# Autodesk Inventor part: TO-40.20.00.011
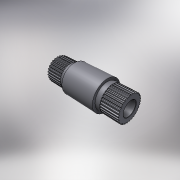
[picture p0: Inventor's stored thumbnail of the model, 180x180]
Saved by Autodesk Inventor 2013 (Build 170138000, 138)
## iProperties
Created: 2012-02
Part Number: TO-40.20.00.011
Material: Steel, Mild
Document SubType Name: Modeling
Designer: tedescj
Mass: 8156.12 g
Surface Area: 1203.33 cm^2
Volume: 1037.67 cm^3
Density: 7.86 g/cm^3
Author: tedescj
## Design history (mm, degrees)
sketch "Sketch1"
  geometry: C1 r 40 at (-44.134, 0) reference; 2 further points
  constraints: 1 centre point, 3 other
extrude "Extrusion1" new body sketch "Sketch1" stored distance "d0" = 242; taper "d1" = 0 deg
sketch "Sketch2"
  geometry: C1 r 48.268 at (-44.134, 0) reference; 1 further point
  constraints: 1 centre point, 2 other
extrude "Extrusion2" join sketch "Sketch2" stored distance "d2" = 106; taper "d3" = 0 deg
feature "Base1"
feature "Base2"
combine "Combine1"
  body "Solid2"
combine "Combine2"
  body "Solid3"
hole "Hole1" diameter "d6" = 45; stored, may be unused: countersink angle "d10" = 90 deg, drill point angle "d12" = 118 deg; dims "d4" = 10, "d5" = 10, "d7" = 6, "d8" = 4, "d9" = 2, "d11" = 8
chamfer "Chamfer1" distance "d13" = 1; stored, may be unused: second distance "d14" = 2, angle "d15" = 45 deg
body "Solid1"
